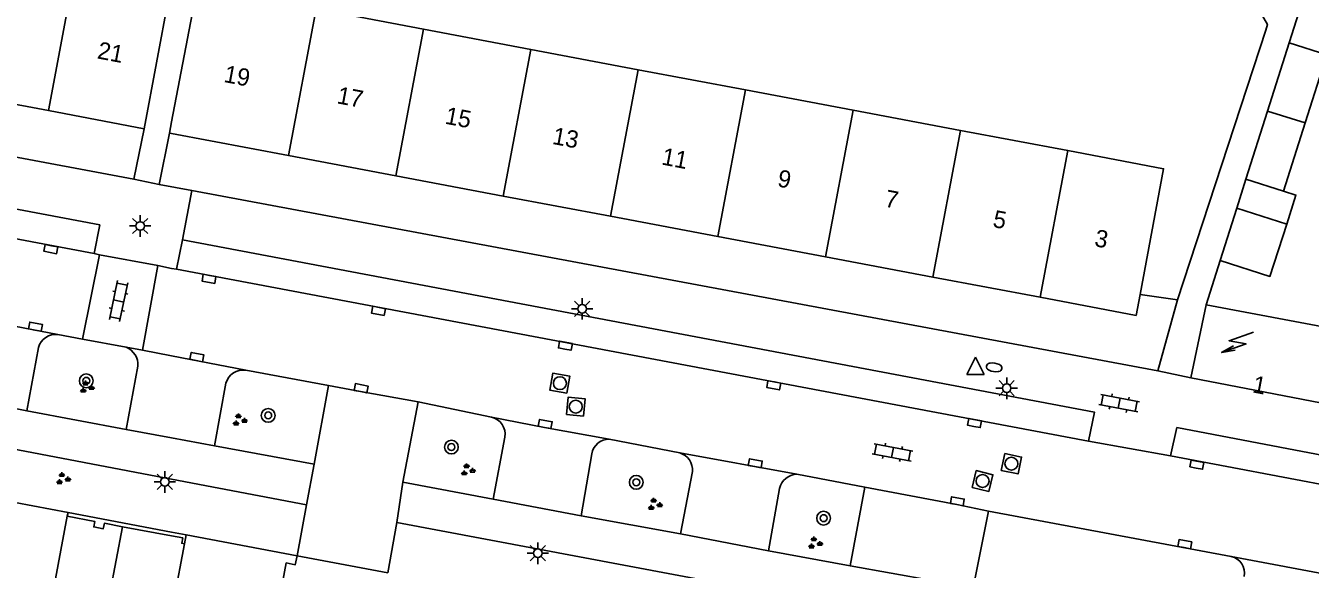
# Model space of a CAD drawing. Extents: x 124000 to 128010, y 398999 to 403000.
# Drawn here: x 126991.5 to 127066.1, y 399109.3 to 399140.9 of the extents above; entities that cross this region are included whole.
import ezdxf

# ---------------------------------------------------------------- set-up
doc = ezdxf.new("R2010")
doc.units = 0
for name, color, linetype in [('gg-afsc-erfafscheiding', 7, 'Continuous'), ('gg-afsc-hekwerk', 7, 'Continuous'), ('gg-afsc-muur', 7, 'Continuous'), ('gg-anno-huisnummerreeks BGT', 7, 'Continuous'), ('gg-bbg-bijgebouw', 7, 'Continuous'), ('gg-bbg-hoofdgebouw', 7, 'Continuous'), ('gg-bbg-luifel en loopbrug', 7, 'Continuous'), ('gg-bbg-tussenscheiding', 7, 'Continuous'), ('gg-knt-verharding', 7, 'Continuous'), ('gg-knt-verharding nz', 7, 'Continuous'), ('gt-grn-weggrens', 7, 'Continuous'), ('gt-symb-boom', 7, 'Continuous'), ('gt-symb-brandkraan', 7, 'Continuous'), ('gt-symb-groenvak', 7, 'Continuous'), ('gt-symb-klinker verharding', 7, 'Continuous'), ('gt-symb-kolk', 7, 'Continuous'), ('gt-symb-lichtmast', 7, 'Continuous'), ('gt-symb-rioolschacht', 7, 'Continuous'), ('gt-symb-trafo symbool', 7, 'Continuous'), ('gt-symb-waterafsluiter', 7, 'Continuous')]:
    doc.layers.add(name, color=color, linetype=linetype)

# ---------------------------------------------------------------- blocks, each defined once
blk = doc.blocks.new('gt0-KOLK')
at = {"layer": 'gt-symb-kolk'}
blk.add_lwpolyline([(0, 0), (0.375, 0), (0.375, 0.4), (-0.375, 0.4), (-0.375, 0), (0, 0)], dxfattribs=at)
blk = doc.blocks.new('gt0-HSP')
at = {"layer": 'gt-symb-trafo symbool'}
for points in [[(0.771, 0.746), (-0.529, -0.004), (0.471, -0.004), (-0.829, -0.754)], [(-0.217, -0.24), (-0.829, -0.754), (-0.077, -0.48)]]:
    blk.add_lwpolyline(points, dxfattribs=at)
blk = doc.blocks.new('gt0-RS')
at = {"layer": 'gt-symb-rioolschacht'}
blk.add_lwpolyline([(-0.5, -0.5), (0.5, -0.5), (0.5, 0.5), (-0.5, 0.5)], close=True, dxfattribs=at)
blk.add_circle((0, 0), 0.375, dxfattribs=at)
blk = doc.blocks.new('gt0-GRVAK')
at = {"layer": 'gt-symb-groenvak'}
for p, q in [((-0.11, 0.189), (-0.228, 0.24)), ((-0.182, 0.153), (0.088, 0.153)), ((-0.091, 0.211), (-0.156, 0.322)), ((-0.047, 0.214), (-0.047, 0.393)), ((-0.004, 0.211), (0.061, 0.322)), ((0.015, 0.189), (0.133, 0.24)), ((0.262, -0.052), (0.197, 0.059)), ((0.305, -0.049), (0.305, 0.13)), ((0.349, -0.052), (0.414, 0.059)), ((-0.245, -0.228), (-0.363, -0.177)), ((-0.318, -0.264), (-0.047, -0.264)), ((-0.226, -0.206), (-0.291, -0.095)), ((-0.183, -0.203), (-0.183, -0.024)), ((-0.139, -0.206), (-0.074, -0.095)), ((-0.12, -0.228), (-0.002, -0.177)), ((0.243, -0.074), (0.125, -0.023)), ((0.17, -0.11), (0.441, -0.11)), ((0.368, -0.074), (0.486, -0.023))]:
    blk.add_line(p, q, dxfattribs=at)
blk = doc.blocks.new('gt0-BOOM')
at = {"layer": 'gt-symb-boom'}
for radius in [0.4, 0.2]:
    blk.add_circle((0, 0), radius, dxfattribs=at)
blk = doc.blocks.new('gt0-KL1')
at = {"layer": 'gt-symb-klinker verharding'}
for p, q in [((-1.15, 0.3), (1.15, 0.3)), ((-1, -0.3), (-1, 0.3)), ((-0.5, 0.3), (-0.5, 0.45)), ((0, -0.3), (0, 0.3)), ((0.5, 0.3), (0.5, 0.45)), ((1, -0.3), (1, 0.3)), ((-1.15, -0.3), (1.15, -0.3)), ((-0.5, -0.45), (-0.5, -0.3)), ((0.5, -0.45), (0.5, -0.3))]:
    blk.add_line(p, q, dxfattribs=at)
blk = doc.blocks.new('gt0-WAFSL')
at = {"layer": 'gt-symb-waterafsluiter'}
for p, q in [((-0.5, -0.333), (0, 0.667)), ((0, 0.667), (0.5, -0.333)), ((0.5, -0.333), (-0.5, -0.333))]:
    blk.add_line(p, q, dxfattribs=at)
blk = doc.blocks.new('gt0-BR')
at = {"layer": 'gt-symb-brandkraan'}
for centre, radius, start, end in [((-0.244, 0), 0.206, 107.56694, 252.43307), ((0.599, -2.664), 3, 106.89205, 107.56694), ((0, -0.691), 0.938, 73.10799, 106.89205), ((-0.599, -2.664), 3, 72.43309, 73.10799), ((0.244, 0), 0.206, 287.56695, 72.43309), ((0.599, 2.664), 3, 252.43307, 253.10797), ((0, 0.691), 0.938, 253.10797, 286.89206), ((-0.599, 2.664), 3, 286.89206, 287.56695)]:
    blk.add_arc(centre, radius, start, end, dxfattribs=at)
blk = doc.blocks.new('gt0-LMAST')
at = {"layer": 'gt-symb-lichtmast'}
for p, q in [((-0.182, 0.173), (-0.447, 0.438)), ((-0.005, 0.246), (-0.005, 0.621)), ((0.172, 0.173), (0.437, 0.438)), ((-0.255, -0.004), (-0.63, -0.004)), ((-0.182, -0.181), (-0.447, -0.446)), ((-0.005, -0.254), (-0.005, -0.629)), ((0.437, -0.446), (0.172, -0.181)), ((0.245, -0.004), (0.62, -0.004))]:
    blk.add_line(p, q, dxfattribs=at)
blk.add_circle((-0.005, -0.004), 0.25, dxfattribs=at)

msp = doc.modelspace()

# ---------------------------------------------------------------- linework, layer by layer
at = {"layer": 'gg-afsc-erfafscheiding'}
for p, q in [((127065.984, 399143.342), (127064.884, 399139.872)), ((127060.064, 399124.668), (127060.877, 399127.232))]:
    msp.add_line(p, q, dxfattribs=at)
at = {"layer": 'gg-afsc-hekwerk'}
for p, q in [((127063.522, 399140.617), (127058.408, 399124.947)), ((127058.408, 399124.947), (127056.225, 399125.275))]:
    msp.add_line(p, q, dxfattribs=at)
at = {"layer": 'gg-afsc-muur'}
for p, q in [((126993.988, 399112.607), (127000, 399111.473)), ((127000, 399111.473), (127000.845, 399111.314))]:
    msp.add_line(p, q, dxfattribs=at)
for points in [[(127063.522, 399140.617), (127063.618, 399140.934), (127063.277, 399141.542), (127057.277, 399143.193)], [(126997.154, 399111.787), (126996.097, 399111.984), (126996.038, 399111.67), (126995.482, 399111.774), (126995.541, 399112.089), (126993.947, 399112.39)]]:
    msp.add_lwpolyline(points, dxfattribs=at)
at = {"layer": 'gg-bbg-bijgebouw'}
for p, q in [((127063.63, 399135.916), (127064.884, 399139.872)), ((127062.376, 399131.96), (127063.63, 399135.916)), ((127065.813, 399135.224), (127064.559, 399131.268)), ((127064.559, 399131.268), (127062.376, 399131.96)), ((127060.877, 399127.232), (127061.841, 399130.273)), ((127061.841, 399130.273), (127064.739, 399129.354)), ((127000.845, 399111.314), (127000.747, 399110.792)), ((127000.845, 399111.314), (127007.291, 399110.098)), ((127000.747, 399110.792), (127000.045, 399107.048))]:
    msp.add_line(p, q, dxfattribs=at)
for points in [[(127064.884, 399139.872), (127067.067, 399139.18), (127065.813, 399135.224)], [(127064.739, 399129.354), (127063.765, 399126.316), (127060.877, 399127.232)], [(127007.291, 399110.098), (127007.178, 399109.572), (127006.66, 399109.683), (127005.958, 399105.942)]]:
    msp.add_lwpolyline(points, dxfattribs=at)
at = {"layer": 'gg-bbg-hoofdgebouw'}
for p, q in [((126998.41, 399134.893), (127000, 399143.433)), ((127001.497, 399143.141), (127000, 399135.29)), ((127014.629, 399140.666), (127008.395, 399141.841)), ((127020.862, 399139.491), (127014.629, 399140.666)), ((127027.095, 399138.317), (127020.862, 399139.491)), ((127033.327, 399137.143), (127027.095, 399138.317)), ((126986.62, 399137.12), (126992.853, 399135.943)), ((127039.561, 399135.968), (127033.327, 399137.143)), ((126992.853, 399135.943), (126998.41, 399134.893)), ((127045.794, 399134.793), (127039.561, 399135.968)), ((126999.875, 399134.634), (127000, 399135.29)), ((127000, 399134.61), (126999.875, 399134.634)), ((127000, 399134.61), (127006.791, 399133.33)), ((127052.027, 399133.619), (127045.794, 399134.793)), ((127006.791, 399133.33), (127013.023, 399132.155)), ((127013.023, 399132.155), (127019.256, 399130.98)), ((127019.256, 399130.98), (127025.49, 399129.805)), ((127025.49, 399129.805), (127031.723, 399128.63)), ((127031.723, 399128.63), (127037.956, 399127.455)), ((127037.956, 399127.455), (127044.188, 399126.281)), ((127044.188, 399126.281), (127050.421, 399125.106)), ((127059.166, 399120.419), (127060.064, 399124.668)), ((127069.456, 399118.456), (127059.166, 399120.419)), ((126993.988, 399112.607), (126990.918, 399113.186)), ((126992.842, 399106.58), (126993.947, 399112.39)), ((126993.947, 399112.39), (126993.988, 399112.607))]:
    msp.add_line(p, q, dxfattribs=at)
for points in [[(127056.225, 399125.275), (127057.597, 399132.569), (127052.027, 399133.619)], [(127050.421, 399125.106), (127055.996, 399124.055), (127056.225, 399125.275)], [(127069.456, 399118.456), (127069.969, 399121.168), (127067.388, 399121.671), (127067.787, 399123.21), (127060.064, 399124.668)]]:
    msp.add_lwpolyline(points, dxfattribs=at)
at = {"layer": 'gg-bbg-luifel en loopbrug'}
for p, q in [((127061.841, 399130.273), (127062.376, 399131.96)), ((127000, 399111.256), (126997.154, 399111.787))]:
    msp.add_line(p, q, dxfattribs=at)
for points in [[(127064.739, 399129.354), (127065.279, 399131.037), (127064.559, 399131.268)], [(126999.712, 399105.273), (126996.047, 399105.97), (126997.154, 399111.787)], [(127000, 399111.256), (127000.648, 399111.135), (127000.59, 399110.821), (127000.747, 399110.792)]]:
    msp.add_lwpolyline(points, dxfattribs=at)
at = {"layer": 'gg-bbg-tussenscheiding'}
for p, q in [((126992.853, 399135.943), (126994.463, 399144.478)), ((127006.791, 399133.33), (127008.395, 399141.841)), ((127013.023, 399132.155), (127014.629, 399140.666)), ((127019.256, 399130.98), (127020.862, 399139.491)), ((127025.49, 399129.805), (127027.095, 399138.317)), ((127031.723, 399128.63), (127033.327, 399137.143)), ((127037.956, 399127.455), (127039.561, 399135.968)), ((127065.813, 399135.224), (127063.63, 399135.916)), ((127044.188, 399126.281), (127045.794, 399134.793)), ((127050.421, 399125.106), (127052.027, 399133.619))]:
    msp.add_line(p, q, dxfattribs=at)
at = {"layer": 'gg-knt-verharding'}
for p, q in [((126939.993, 399142.798), (126997.812, 399131.957)), ((126997.812, 399131.957), (126998.41, 399134.893)), ((126999.875, 399134.634), (126999.286, 399131.657)), ((126997.812, 399131.957), (126999.286, 399131.657)), ((127001.174, 399131.305), (126999.286, 399131.657)), ((127057.26, 399120.833), (127001.174, 399131.305)), ((126995.503, 399127.639), (126995.843, 399129.312)), ((127000.283, 399126.729), (127000.63, 399128.439)), ((126994.835, 399122.682), (126995.813, 399127.572)), ((126995.813, 399127.572), (126995.503, 399127.639)), ((126999.197, 399126.944), (126995.813, 399127.572)), ((126999.197, 399126.944), (126998.308, 399122.025)), ((126999.197, 399126.944), (127000, 399126.785)), ((127000, 399126.785), (127000.283, 399126.729)), ((127058.408, 399124.947), (127057.26, 399120.833)), ((126993.401, 399122.944), (126994.835, 399122.682)), ((126997.358, 399122.204), (126994.835, 399122.682)), ((126991.598, 399118.518), (126992.273, 399122.18)), ((126998.308, 399122.025), (126997.358, 399122.204)), ((126998.049, 399121.113), (126997.362, 399117.425)), ((127004.314, 399120.866), (127009.102, 399119.985)), ((127002.486, 399116.481), (127003.155, 399120.111)), ((127057.26, 399120.833), (127059.166, 399120.419)), ((127009.102, 399119.985), (127008.27, 399115.409)), ((127010.967, 399119.627), (127009.102, 399119.985)), ((127010.967, 399119.627), (127014.317, 399119.03)), ((127014.317, 399119.03), (127013.429, 399114.379)), ((127018.564, 399118.148), (127014.317, 399119.03)), ((126980.849, 399118.178), (127000, 399114.544)), ((126997.362, 399117.425), (126991.598, 399118.518)), ((127008.27, 399115.409), (127002.486, 399116.481)), ((127018.661, 399113.385), (127019.349, 399116.988)), ((127029.501, 399116.066), (127025.414, 399116.865)), ((127058, 399115.907), (127053.241, 399116.754)), ((127024.399, 399116.013), (127023.772, 399112.419)), ((127029.543, 399111.375), (127030.236, 399114.989)), ((127000, 399114.544), (127007.842, 399113.056)), ((127013.429, 399114.379), (127018.661, 399113.385)), ((127036.3, 399114.828), (127040.241, 399114.071)), ((127035.303, 399114.008), (127034.646, 399110.392)), ((127039.406, 399109.514), (127040.241, 399114.071)), ((127007.842, 399113.056), (127007.291, 399110.098)), ((127047.423, 399112.697), (127046.532, 399108.229)), ((127061.522, 399110.061), (127047.423, 399112.697)), ((127012.549, 399109.11), (127013.082, 399112.03)), ((127023.772, 399112.419), (127029.543, 399111.375)), ((127034.646, 399110.392), (127039.406, 399109.514))]:
    msp.add_line(p, q, dxfattribs=at)
for points in [[(126995.843, 399129.312), (126940.909, 399139.654), (126940.546, 399138.07)], [(127053.241, 399116.754), (127053.59, 399118.432), (127000.63, 399128.439)], [(127058, 399115.907), (127058.37, 399117.536), (127078.829, 399113.638)], [(127040.241, 399114.071), (127045.581, 399113.065), (127047.423, 399112.697)], [(127013.082, 399112.03), (127039.742, 399107.023), (127039.252, 399104.086)]]:
    msp.add_lwpolyline(points, dxfattribs=at)
for centre, radius, start, end in [((126993.268, 399121.926), 1.027, 82.54854, 165.67142), ((126996.944, 399121.178), 1.107, 356.65066, 68.04673), ((127004.147, 399119.856), 1.024, 80.58741, 165.57494), ((127018.347, 399117.156), 1.016, 350.5049, 77.66942), ((127025.394, 399115.858), 1.007, 88.87978, 171.14101), ((127029.234, 399115.095), 1.007, 353.9725, 74.65076), ((127036.318, 399113.79), 1.039, 91.01464, 167.85772), ((127061.298, 399109.091), 0.995, 349.16467, 77.01873)]:
    msp.add_arc(centre, radius, start, end, dxfattribs=at)
at = {"layer": 'gg-knt-verharding nz'}
for p, q in [((126940.546, 399138.07), (126995.503, 399127.639)), ((127000.283, 399126.729), (127053.241, 399116.754)), ((126993.401, 399122.944), (126986.527, 399124.237)), ((127000, 399121.705), (126998.308, 399122.025)), ((127004.314, 399120.866), (127000, 399121.705)), ((126986.45, 399119.502), (126991.598, 399118.518)), ((126997.362, 399117.425), (127000, 399116.939)), ((127000, 399116.939), (127002.486, 399116.481)), ((127029.501, 399116.066), (127036.3, 399114.828)), ((127058, 399115.907), (127077.545, 399112.182)), ((127008.27, 399115.409), (127007.842, 399113.056)), ((127013.429, 399114.379), (127013.082, 399112.03)), ((127018.661, 399113.385), (127023.772, 399112.419)), ((127029.543, 399111.375), (127034.646, 399110.392)), ((127068.544, 399108.734), (127061.522, 399110.061)), ((127039.406, 399109.514), (127046.532, 399108.229))]:
    msp.add_line(p, q, dxfattribs=at)
msp.add_lwpolyline([(127018.564, 399118.148), (127021.655, 399117.553), (127025.414, 399116.865)], dxfattribs=at)
at = {"layer": 'gt-grn-weggrens'}
for p, q in [((127000.63, 399128.439), (127001.174, 399131.305)), ((127012.549, 399109.11), (127007.291, 399110.098))]:
    msp.add_line(p, q, dxfattribs=at)

# ---------------------------------------------------------------- block references
at = {"layer": 'gt-symb-boom'}
for p in [(126995.049, 399120.256), (127005.609, 399118.249), (127016.246, 399116.409), (127026.978, 399114.362), (127037.853, 399112.281)]:
    msp.add_blockref('gt0-BOOM', p, dxfattribs=at)
at = {"layer": 'gt-symb-brandkraan', "rotation": -8.680850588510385}
msp.add_blockref('gt0-BR', (127047.76, 399121.037), dxfattribs=at)
at = {"layer": 'gt-symb-groenvak'}
for p in [(126995.054, 399119.872), (127003.929, 399117.969), (126993.679, 399114.561), (127017.174, 399115.071), (127028.035, 399113.073), (127037.336, 399110.825)]:
    msp.add_blockref('gt0-GRVAK', p, dxfattribs=at)
at = {"layer": 'gt-symb-klinker verharding'}
for p, rotation in [((126996.925, 399124.887), 78.22937399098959), ((127055.014, 399118.955), -10.71464389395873), ((127041.856, 399116.097), 169.34163849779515)]:
    msp.add_blockref('gt0-KL1', p, dxfattribs=dict(at, rotation=rotation))
at = {"layer": 'gt-symb-kolk'}
for p, rotation in [((126993.027, 399128.099), 169.28535610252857), ((127002.209, 399126.371), 169.45426563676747), ((127012.045, 399124.511), 169.2853561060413), ((126992.055, 399123.202), -10.837910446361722), ((127022.823, 399122.097), -10.837910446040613), ((127001.436, 399121.434), -11.186329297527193), ((127010.967, 399119.627), -10.950434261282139), ((127034.994, 399120.191), 169.34163849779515), ((127021.655, 399117.553), -10.894182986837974), ((127046.581, 399117.606), -10.837910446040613), ((127033.851, 399115.271), -10.366322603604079), ((127059.486, 399115.193), -11.073871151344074), ((127045.581, 399113.065), -10.658361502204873), ((127058.788, 399110.574), -10.658361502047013)]:
    msp.add_blockref('gt0-KOLK', p, dxfattribs=dict(at, rotation=rotation))
at = {"layer": 'gt-symb-lichtmast'}
for p in [(126998.179, 399129.247), (127023.846, 399124.436), (127048.488, 399119.827), (126999.615, 399114.39), (127021.27, 399110.249)]:
    msp.add_blockref('gt0-LMAST', p, dxfattribs=at)
at = {"layer": 'gt-symb-rioolschacht'}
for p, rotation in [((127022.544, 399120.117), 80.49998940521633), ((127023.467, 399118.753), -5.739098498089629), ((127048.756, 399115.443), -101.65840162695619), ((127047.082, 399114.436), -13.48012621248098)]:
    msp.add_blockref('gt0-RS', p, dxfattribs=dict(at, rotation=rotation))
at = {"layer": 'gt-symb-trafo symbool', "rotation": -10.71464389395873}
msp.add_blockref('gt0-HSP', (127061.918, 399122.489), dxfattribs=at)
at = {"layer": 'gt-symb-waterafsluiter'}
msp.add_blockref('gt0-WAFSL', (127046.675, 399120.954), dxfattribs=at)

# ---------------------------------------------------------------- texts
at = {"layer": 'gg-anno-huisnummerreeks BGT'}
for s, p in [('21', (126995.641, 399138.978)), ('19', (127002.987, 399137.609)), ('17', (127009.556, 399136.371)), ('15', (127015.829, 399135.188)), ('13', (127022.062, 399134.013)), ('11', (127028.401, 399132.819)), ('9', (127035.129, 399131.55)), ('7', (127041.357, 399130.376)), ('5', (127047.63, 399129.194)), ('3', (127053.533, 399128.081)), ('1', (127062.706, 399119.59))]:
    msp.add_text(s, height=1, rotation=349.3, dxfattribs=at).set_placement(p)

doc.saveas('drawing.dxf')
